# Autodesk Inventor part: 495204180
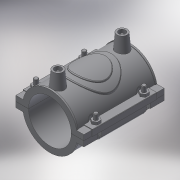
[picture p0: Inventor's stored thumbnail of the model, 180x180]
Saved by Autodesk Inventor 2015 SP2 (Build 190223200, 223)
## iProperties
Created: 2017-07
Part Number: 495204180
Material: Generic
Description: PLASSON REPAIR SADDLE 180
Document SubType Name: Modeling
Designer: KIM
Density: 1 g/cm^3
Appearance: Default
Author: KIM
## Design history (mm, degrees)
derived "495204.ipt"
feature "Solid1::495204.ipt"
tag "TaggingFeature1"
body "Solid1"
other parameters: "d1" = 207, "d2" = 219, "d3" = 45, "d4" = 118, "d5" = 0, "d6" = 0.1, "d8" = 0, "d19" = 6, "d20" = 6, "d21" = 70.8, "d23" = 0, "d24" = 35.4, "d26" = 0, "d27" = 3, "d28" = 3, "d29" = 3, "d31" = 6, "d32" = 0, "d33" = 0, "d34" = 0.6, "d40" = 107.64, "d41" = 64.9, "d43" = 0, "d45" = 0, "d47" = 111.78, "d48" = 47.2, "d50" = 0, "d70" = 15, "d72" = 0, "d73" = 6, "d75" = 5, "d76" = 0, "d77" = 9, "d78" = 119, "d79" = 15, "d80" = 47.2, "d82" = 5 deg, "d84" = 4, "d85" = 14, "d86" = 0, "d87" = 3, "d88" = 0, "d89" = 1, "d90" = 1, "d91" = 94.4, "d92" = 0, "d93" = 0.5, "d94" = 94.73684, "d96" = 211.14, "d97" = 2.36, "d98" = 0, "d99" = 47.2, "d100" = 0, "d102" = 3.54, "B_" = 219, "H_" = 29, "L_" = 118, "d_t" = 6
